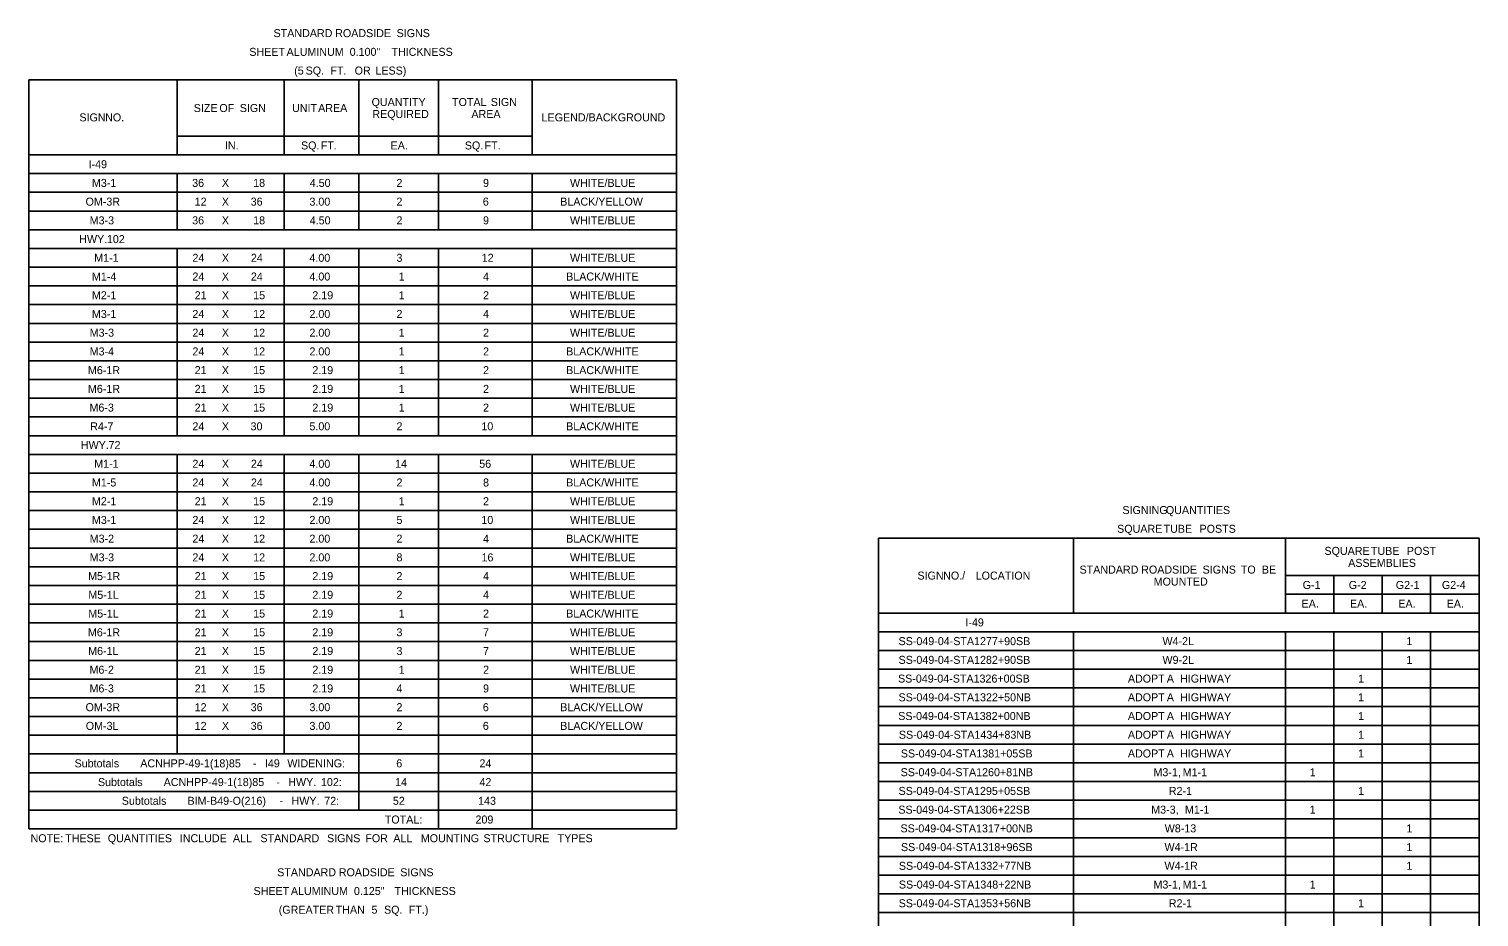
# Model space of a CAD drawing. Extents: x 1226613 to 1228135, y 151309 to 152326.
# Drawn here: x 1226613 to 1227428, y 151827 to 152326 of the extents above; entities that cross this region are included whole.
import ezdxf

# ---------------------------------------------------------------- set-up
doc = ezdxf.new("R2010")
doc.units = 0
doc.layers.add('R_Dimension', color=7, linetype='Continuous')

msp = doc.modelspace()

# ---------------------------------------------------------------- linework, layer by layer
at = {"layer": 'R_Dimension'}
for p, q in [((1226612.74, 152297.31), (1226976.91, 152297.31)), ((1226612.74, 151876.11), (1226612.74, 152297.31)), ((1226696.11, 152255.19), (1226696.11, 152297.31)), ((1226756.21, 152255.19), (1226756.21, 152297.31)), ((1226798.33, 152255.19), (1226798.33, 152297.31)), ((1226843.09, 152255.19), (1226843.09, 152297.31)), ((1226895.74, 152255.19), (1226895.74, 152297.31)), ((1226976.91, 151876.11), (1226976.91, 152297.31)), ((1226696.11, 152265.72), (1226895.74, 152265.72)), ((1226612.74, 152255.19), (1226976.91, 152255.19)), ((1226895.74, 152255.19), (1226976.91, 152255.19)), ((1226612.74, 152244.66), (1226976.91, 152244.66)), ((1226696.11, 152213.07), (1226696.11, 152244.66)), ((1226756.21, 152213.07), (1226756.21, 152244.66)), ((1226798.33, 152213.07), (1226798.33, 152244.66)), ((1226843.09, 152213.07), (1226843.09, 152244.66)), ((1226895.74, 152213.07), (1226895.74, 152244.66)), ((1226612.74, 152234.13), (1226976.91, 152234.13)), ((1226612.74, 152223.6), (1226976.91, 152223.6)), ((1226612.74, 152213.07), (1226976.91, 152213.07)), ((1226612.74, 152202.54), (1226976.91, 152202.54)), ((1226696.11, 152097.24), (1226696.11, 152202.54)), ((1226756.21, 152097.24), (1226756.21, 152202.54)), ((1226798.33, 152097.24), (1226798.33, 152202.54)), ((1226843.09, 152097.24), (1226843.09, 152202.54)), ((1226895.74, 152097.24), (1226895.74, 152202.54)), ((1226612.74, 152192.01), (1226976.91, 152192.01)), ((1226612.74, 152181.48), (1226976.91, 152181.48)), ((1226612.74, 152170.95), (1226976.91, 152170.95)), ((1226612.74, 152160.42), (1226976.91, 152160.42)), ((1226612.74, 152149.89), (1226976.91, 152149.89)), ((1226612.74, 152139.36), (1226976.91, 152139.36)), ((1226612.74, 152128.83), (1226976.91, 152128.83)), ((1226612.74, 152118.3), (1226976.91, 152118.3)), ((1226612.74, 152107.77), (1226976.91, 152107.77)), ((1226612.74, 152097.24), (1226976.91, 152097.24)), ((1226612.74, 152086.71), (1226976.91, 152086.71)), ((1226696.11, 151918.23), (1226696.11, 152086.71)), ((1226756.21, 151918.23), (1226756.21, 152086.71)), ((1226798.33, 151886.64), (1226798.33, 152086.71)), ((1226843.09, 151876.11), (1226843.09, 152086.71)), ((1226895.74, 151876.11), (1226895.74, 152086.71)), ((1226612.74, 152076.18), (1226976.91, 152076.18)), ((1226612.74, 152065.65), (1226976.91, 152065.65)), ((1226612.74, 152055.12), (1226976.91, 152055.12)), ((1226612.74, 152044.59), (1226976.91, 152044.59)), ((1227090.5, 152039.62), (1227428.34, 152039.62)), ((1227090.5, 151597.36), (1227090.5, 152039.62)), ((1227200.19, 151997.5), (1227200.19, 152039.62)), ((1227319.53, 151997.5), (1227319.53, 152039.62)), ((1227428.34, 151597.36), (1227428.34, 152039.62)), ((1226612.74, 152034.06), (1226976.91, 152034.06)), ((1226612.74, 152023.53), (1226976.91, 152023.53)), ((1227319.53, 152018.56), (1227428.34, 152018.56)), ((1227346.73, 151997.5), (1227346.73, 152018.56)), ((1227373.93, 151997.5), (1227373.93, 152018.56)), ((1227401.13, 151997.5), (1227401.13, 152018.56)), ((1226612.74, 152013), (1226976.91, 152013)), ((1226612.74, 152002.47), (1226976.91, 152002.47)), ((1227319.53, 152008.03), (1227428.34, 152008.03)), ((1227090.5, 151997.5), (1227428.34, 151997.5)), ((1226612.74, 151991.94), (1226976.91, 151991.94)), ((1227090.5, 151986.97), (1227428.34, 151986.97)), ((1227200.19, 151713.19), (1227200.19, 151986.97)), ((1227319.53, 151713.19), (1227319.53, 151986.97)), ((1227346.73, 151713.19), (1227346.73, 151986.97)), ((1227373.93, 151713.19), (1227373.93, 151986.97)), ((1227401.13, 151713.19), (1227401.13, 151986.97)), ((1226612.74, 151981.41), (1226976.91, 151981.41)), ((1226612.74, 151970.88), (1226976.91, 151970.88)), ((1227090.5, 151976.44), (1227428.34, 151976.44)), ((1227090.5, 151965.91), (1227428.34, 151965.91)), ((1226612.74, 151960.35), (1226976.91, 151960.35)), ((1227090.5, 151955.38), (1227428.34, 151955.38)), ((1226612.74, 151949.82), (1226976.91, 151949.82)), ((1226612.74, 151939.29), (1226976.91, 151939.29)), ((1227090.5, 151944.85), (1227428.34, 151944.85)), ((1226612.74, 151928.76), (1226976.91, 151928.76)), ((1227090.5, 151934.32), (1227428.34, 151934.32)), ((1227090.5, 151923.79), (1227428.34, 151923.79)), ((1226612.74, 151918.23), (1226976.91, 151918.23)), ((1227090.5, 151913.26), (1227428.34, 151913.26)), ((1226612.74, 151907.7), (1226976.91, 151907.7)), ((1226612.74, 151897.17), (1226976.91, 151897.17)), ((1227090.5, 151902.73), (1227428.34, 151902.73)), ((1227090.5, 151892.2), (1227428.34, 151892.2)), ((1226612.74, 151886.64), (1226976.91, 151886.64)), ((1227090.5, 151881.67), (1227428.34, 151881.67)), ((1226612.74, 151876.11), (1226976.91, 151876.11)), ((1227090.5, 151871.14), (1227428.34, 151871.14)), ((1227090.5, 151860.61), (1227428.34, 151860.61)), ((1227090.5, 151850.08), (1227428.34, 151850.08)), ((1227090.5, 151839.55), (1227428.34, 151839.55)), ((1227090.5, 151829.02), (1227428.34, 151829.02))]:
    msp.add_line(p, q, dxfattribs=at)

# ---------------------------------------------------------------- texts
for s, p in [('STANDARD', (1226750.3, 152321.39)), (' ROADSIDE', (1226783.29, 152321.39)), (' SIGNS', (1226817.84, 152321.39)), ('SHEET', (1226736.66, 152310.86)), (' ALUMINUM', (1226755.97, 152310.86)), (' 0.100"', (1226791.44, 152310.86)), (' THICKNESS', (1226814.97, 152310.86)), ('(5', (1226761.92, 152300.33)), (' SQ.', (1226766.67, 152300.33)), (' FT.', (1226780.6, 152300.33)), (' OR', (1226794.24, 152300.33)), (' LESS)', (1226805.93, 152300.33)), ('SIZE', (1226705.4, 152279.27)), (' OF', (1226718.15, 152279.27)), (' SIGN', (1226729.63, 152279.27)), ('UNIT', (1226760.71, 152279.27)), (' AREA', (1226773.71, 152279.27)), ('QUANTITY', (1226805.44, 152282.64)), ('REQUIRED', (1226805.88, 152275.89)), ('TOTAL', (1226850.7, 152282.64)), ('AREA', (1226861.6, 152275.89)), (' SIGN', (1226870.83, 152282.64)), ('SIGN', (1226641.1, 152274)), (' NO.', (1226653.89, 152274)), ('LEGEND/BACKGROUND', (1226901.08, 152274)), ('IN.', (1226722.94, 152258.21)), ('SQ.', (1226765.74, 152258.21)), (' FT.', (1226775.17, 152258.21)), ('EA.', (1226816.14, 152258.21)), ('SQ.', (1226857.88, 152258.21)), (' FT.', (1226867.3, 152258.21)), ('I-49', (1226646.27, 152247.68)), ('M3-1', (1226648.15, 152237.15)), ('36', (1226704.53, 152237.15)), ('X', (1226721.23, 152237.15)), ('18', (1226738.84, 152237.15)), ('4.50', (1226770.67, 152237.15)), ('2', (1226819.44, 152237.15)), ('9', (1226868.12, 152237.15)), ('WHITE/BLUE', (1226917.05, 152237.15)), ('OM-3R', (1226644.56, 152226.62)), ('12', (1226705.93, 152226.62)), ('X', (1226721.23, 152226.62)), ('36', (1226737.44, 152226.62)), ('3.00', (1226770.49, 152226.62)), ('2', (1226819.44, 152226.62)), ('6', (1226868.01, 152226.62)), ('BLACK/YELLOW', (1226911.55, 152226.62)), ('M3-3', (1226646.88, 152216.09)), ('36', (1226704.53, 152216.09)), ('X', (1226721.23, 152216.09)), ('18', (1226738.84, 152216.09)), ('4.50', (1226770.67, 152216.09)), ('2', (1226819.44, 152216.09)), ('9', (1226868.12, 152216.09)), ('WHITE/BLUE', (1226917.05, 152216.09)), ('HWY.', (1226641.01, 152205.56)), (' 102', (1226654.9, 152205.56)), ('M1-1', (1226649.43, 152195.03)), ('24', (1226704.66, 152195.03)), ('X', (1226721.23, 152195.03)), ('24', (1226737.56, 152195.03)), ('4.00', (1226770.49, 152195.03)), ('3', (1226819.44, 152195.03)), ('12', (1226867.39, 152195.03)), ('WHITE/BLUE', (1226917.05, 152195.03)), ('M1-4', (1226648.15, 152184.5)), ('24', (1226704.66, 152184.5)), ('X', (1226721.23, 152184.5)), ('24', (1226737.56, 152184.5)), ('4.00', (1226770.49, 152184.5)), ('1', (1226820.71, 152184.5)), ('4', (1226868.14, 152184.5)), ('BLACK/WHITE', (1226914.88, 152184.5)), ('M2-1', (1226648.15, 152173.97)), ('21', (1226705.93, 152173.97)), ('X', (1226721.23, 152173.97)), ('15', (1226738.84, 152173.97)), ('2.19', (1226772.12, 152173.97)), ('1', (1226820.71, 152173.97)), ('2', (1226868.14, 152173.97)), ('WHITE/BLUE', (1226917.05, 152173.97)), ('M3-1', (1226648.15, 152163.44)), ('24', (1226704.66, 152163.44)), ('X', (1226721.23, 152163.44)), ('12', (1226738.84, 152163.44)), ('2.00', (1226770.49, 152163.44)), ('2', (1226819.44, 152163.44)), ('4', (1226868.14, 152163.44)), ('WHITE/BLUE', (1226917.05, 152163.44)), ('M3-3', (1226646.88, 152152.91)), ('24', (1226704.66, 152152.91)), ('X', (1226721.23, 152152.91)), ('12', (1226738.84, 152152.91)), ('2.00', (1226770.49, 152152.91)), ('1', (1226820.71, 152152.91)), ('2', (1226868.14, 152152.91)), ('WHITE/BLUE', (1226917.05, 152152.91)), ('M3-4', (1226646.88, 152142.38)), ('24', (1226704.66, 152142.38)), ('X', (1226721.23, 152142.38)), ('12', (1226738.84, 152142.38)), ('2.00', (1226770.49, 152142.38)), ('1', (1226820.71, 152142.38)), ('2', (1226868.14, 152142.38)), ('BLACK/WHITE', (1226914.88, 152142.38)), ('M6-1R', (1226645.9, 152131.85)), ('21', (1226705.93, 152131.85)), ('X', (1226721.23, 152131.85)), ('15', (1226738.84, 152131.85)), ('2.19', (1226772.12, 152131.85)), ('1', (1226820.71, 152131.85)), ('2', (1226868.14, 152131.85)), ('BLACK/WHITE', (1226914.88, 152131.85)), ('M6-1R', (1226645.9, 152121.32)), ('21', (1226705.93, 152121.32)), ('X', (1226721.23, 152121.32)), ('15', (1226738.84, 152121.32)), ('2.19', (1226772.12, 152121.32)), ('1', (1226820.71, 152121.32)), ('2', (1226868.14, 152121.32)), ('WHITE/BLUE', (1226917.05, 152121.32)), ('M6-3', (1226646.77, 152110.79)), ('21', (1226705.93, 152110.79)), ('X', (1226721.23, 152110.79)), ('15', (1226738.84, 152110.79)), ('2.19', (1226772.12, 152110.79)), ('1', (1226820.71, 152110.79)), ('2', (1226868.14, 152110.79)), ('WHITE/BLUE', (1226917.05, 152110.79)), ('R4-7', (1226647.16, 152100.26)), ('24', (1226704.66, 152100.26)), ('X', (1226721.23, 152100.26)), ('30', (1226737.37, 152100.26)), ('5.00', (1226770.49, 152100.26)), ('2', (1226819.44, 152100.26)), ('10', (1226867.2, 152100.26)), ('BLACK/WHITE', (1226914.88, 152100.26)), ('HWY.', (1226641.93, 152089.73)), (' 72', (1226655.82, 152089.73)), ('M1-1', (1226649.43, 152079.2)), ('24', (1226704.66, 152079.2)), ('X', (1226721.23, 152079.2)), ('24', (1226737.56, 152079.2)), ('4.00', (1226770.49, 152079.2)), ('14', (1226818.69, 152079.2)), ('56', (1226865.99, 152079.2)), ('WHITE/BLUE', (1226917.05, 152079.2)), ('M1-5', (1226648.15, 152068.67)), ('24', (1226704.66, 152068.67)), ('X', (1226721.23, 152068.67)), ('24', (1226737.56, 152068.67)), ('4.00', (1226770.49, 152068.67)), ('2', (1226819.44, 152068.67)), ('8', (1226868.14, 152068.67)), ('BLACK/WHITE', (1226914.88, 152068.67)), ('M2-1', (1226648.15, 152058.14)), ('21', (1226705.93, 152058.14)), ('X', (1226721.23, 152058.14)), ('15', (1226738.84, 152058.14)), ('2.19', (1226772.12, 152058.14)), ('1', (1226820.71, 152058.14)), ('2', (1226868.14, 152058.14)), ('WHITE/BLUE', (1226917.05, 152058.14)), ('M3-1', (1226648.15, 152047.61)), ('24', (1226704.66, 152047.61)), ('X', (1226721.23, 152047.61)), ('12', (1226738.84, 152047.61)), ('2.00', (1226770.49, 152047.61)), ('5', (1226819.44, 152047.61)), ('10', (1226867.2, 152047.61)), ('WHITE/BLUE', (1226917.05, 152047.61)), ('SIGNING', (1227227.78, 152053.16)), (' QUANTITIES', (1227250.56, 152053.16)), ('SQUARE', (1227224.8, 152042.63)), (' TUBE', (1227249.25, 152042.63)), (' POSTS', (1227269.48, 152042.63)), ('M3-2', (1226646.88, 152037.08)), ('24', (1226704.66, 152037.08)), ('X', (1226721.23, 152037.08)), ('12', (1226738.84, 152037.08)), ('2.00', (1226770.49, 152037.08)), ('2', (1226819.44, 152037.08)), ('4', (1226868.14, 152037.08)), ('BLACK/WHITE', (1226914.88, 152037.08)), ('SQUARE', (1227341.42, 152030.21)), (' TUBE', (1227365.87, 152030.21)), (' POST', (1227386.1, 152030.21)), ('M3-3', (1226646.88, 152026.55)), ('24', (1226704.66, 152026.55)), ('X', (1226721.23, 152026.55)), ('12', (1226738.84, 152026.55)), ('2.00', (1226770.49, 152026.55)), ('8', (1226819.44, 152026.55)), ('16', (1226867.27, 152026.55)), ('WHITE/BLUE', (1226917.05, 152026.55)), ('ASSEMBLIES', (1227354.76, 152023.46)), ('M5-1R', (1226646.01, 152016.02)), ('21', (1226705.93, 152016.02)), ('X', (1226721.23, 152016.02)), ('15', (1226738.84, 152016.02)), ('2.19', (1226772.12, 152016.02)), ('2', (1226819.44, 152016.02)), ('4', (1226868.14, 152016.02)), ('WHITE/BLUE', (1226917.05, 152016.02)), ('SIGN', (1227112.48, 152016.31)), (' NO./', (1227125.27, 152016.31)), (' LOCATION', (1227143.55, 152016.31)), ('STANDARD', (1227203.66, 152019.68)), (' ROADSIDE', (1227236.65, 152019.68)), (' SIGNS', (1227271.19, 152019.68)), (' TO', (1227292.7, 152019.68)), (' BE', (1227304.54, 152019.68)), ('WHITE/BLUE', (1226917.05, 152005.49)), ('MOUNTED', (1227245.35, 152012.93)), ('G-1', (1227329.16, 152011.04)), ('G-2', (1227355.09, 152011.04)), ('G2-1', (1227381.54, 152011.04)), ('G2-4', (1227407.47, 152011.04)), ('M5-1L', (1226646.13, 152005.49)), ('21', (1226705.93, 152005.49)), ('X', (1226721.23, 152005.49)), ('15', (1226738.84, 152005.49)), ('2.19', (1226772.12, 152005.49)), ('2', (1226819.44, 152005.49)), ('4', (1226868.14, 152005.49)), ('EA.', (1227328.56, 152000.51)), ('EA.', (1227355.76, 152000.51)), ('EA.', (1227382.96, 152000.51)), ('EA.', (1227410.16, 152000.51)), ('M5-1L', (1226646.13, 151994.96)), ('21', (1226705.93, 151994.96)), ('X', (1226721.23, 151994.96)), ('15', (1226738.84, 151994.96)), ('2.19', (1226772.12, 151994.96)), ('1', (1226820.71, 151994.96)), ('2', (1226868.14, 151994.96)), ('BLACK/WHITE', (1226914.88, 151994.96)), ('I-49', (1227139.44, 151989.98)), ('M6-1R', (1226645.9, 151984.43)), ('21', (1226705.93, 151984.43)), ('X', (1226721.23, 151984.43)), ('15', (1226738.84, 151984.43)), ('2.19', (1226772.12, 151984.43)), ('3', (1226819.44, 151984.43)), ('7', (1226868.14, 151984.43)), ('WHITE/BLUE', (1226917.05, 151984.43)), ('M6-1L', (1226646.03, 151973.9)), ('21', (1226705.93, 151973.9)), ('X', (1226721.23, 151973.9)), ('15', (1226738.84, 151973.9)), ('2.19', (1226772.12, 151973.9)), ('3', (1226819.44, 151973.9)), ('7', (1226868.14, 151973.9)), ('WHITE/BLUE', (1226917.05, 151973.9)), ('SS-049-04-STA1277+90SB', (1227101.85, 151979.45)), ('W4-2L', (1227250.29, 151979.45)), ('1', (1227387.53, 151979.45)), ('SS-049-04-STA1282+90SB', (1227101.85, 151968.92)), ('W9-2L', (1227250.29, 151968.92)), ('1', (1227387.53, 151968.92)), ('M6-2', (1226646.77, 151963.37)), ('21', (1226705.93, 151963.37)), ('X', (1226721.23, 151963.37)), ('15', (1226738.84, 151963.37)), ('2.19', (1226772.12, 151963.37)), ('1', (1226820.71, 151963.37)), ('2', (1226868.14, 151963.37)), ('WHITE/BLUE', (1226917.05, 151963.37)), ('SS-049-04-STA1326+00SB', (1227101.56, 151958.39)), ('ADOPT', (1227230.84, 151958.39)), (' A', (1227251.07, 151958.39)), (' HIGHWAY', (1227258.51, 151958.39)), ('1', (1227360.33, 151958.39)), ('M6-3', (1226646.77, 151952.84)), ('21', (1226705.93, 151952.84)), ('X', (1226721.23, 151952.84)), ('15', (1226738.84, 151952.84)), ('2.19', (1226772.12, 151952.84)), ('4', (1226819.44, 151952.84)), ('9', (1226868.12, 151952.84)), ('WHITE/BLUE', (1226917.05, 151952.84)), ('OM-3R', (1226644.56, 151942.31)), ('12', (1226705.93, 151942.31)), ('X', (1226721.23, 151942.31)), ('36', (1226737.44, 151942.31)), ('3.00', (1226770.49, 151942.31)), ('2', (1226819.44, 151942.31)), ('6', (1226868.01, 151942.31)), ('BLACK/YELLOW', (1226911.55, 151942.31)), ('SS-049-04-STA1322+50NB', (1227101.85, 151947.86)), ('ADOPT', (1227230.84, 151947.86)), (' A', (1227251.07, 151947.86)), (' HIGHWAY', (1227258.51, 151947.86)), ('1', (1227360.33, 151947.86)), ('SS-049-04-STA1382+00NB', (1227101.67, 151937.33)), ('ADOPT', (1227230.84, 151937.33)), (' A', (1227251.07, 151937.33)), (' HIGHWAY', (1227258.51, 151937.33)), ('1', (1227360.33, 151937.33)), ('OM-3L', (1226644.68, 151931.78)), ('12', (1226705.93, 151931.78)), ('X', (1226721.23, 151931.78)), ('36', (1226737.44, 151931.78)), ('3.00', (1226770.49, 151931.78)), ('2', (1226819.44, 151931.78)), ('6', (1226868.01, 151931.78)), ('BLACK/YELLOW', (1226911.55, 151931.78)), ('SS-049-04-STA1434+83NB', (1227102.03, 151926.8)), ('ADOPT', (1227230.84, 151926.8)), (' A', (1227251.07, 151926.8)), (' HIGHWAY', (1227258.51, 151926.8)), ('1', (1227360.33, 151926.8)), ('SS-049-04-STA1381+05SB', (1227103.12, 151916.27)), ('ADOPT', (1227230.84, 151916.27)), (' A', (1227251.07, 151916.27)), (' HIGHWAY', (1227258.51, 151916.27)), ('1', (1227360.33, 151916.27)), ('Subtotals', (1226638.39, 151910.72)), (' ACNHPP-49-1(18)85', (1226673.68, 151910.72)), (' -', (1226737.07, 151910.72)), (' I49', (1226743.77, 151910.72)), (' WIDENING:', (1226756.39, 151910.72)), ('6', (1226819.31, 151910.72)), ('24', (1226866.12, 151910.72)), ('Subtotals', (1226651.54, 151900.19)), (' ACNHPP-49-1(18)85', (1226686.83, 151900.19)), (' HWY.', (1226756.92, 151900.19)), (' 102:', (1226775.31, 151900.19)), ('14', (1226818.69, 151900.19)), ('42', (1226866.12, 151900.19)), ('SS-049-04-STA1260+81NB', (1227103.02, 151905.74)), ('M3-1,', (1227245.24, 151905.74)), (' M1-1', (1227259.98, 151905.74)), ('1', (1227333.13, 151905.74)), (' -', (1226750.22, 151900.19)), ('SS-049-04-STA1295+05SB', (1227101.85, 151895.21)), ('R2-1', (1227253.87, 151895.21)), ('1', (1227360.33, 151895.21)), ('Subtotals', (1226664.93, 151889.66)), (' BIM-B49-O(216)', (1226700.22, 151889.66)), (' -', (1226752.06, 151889.66)), (' HWY.', (1226758.76, 151889.66)), (' 72:', (1226777.15, 151889.66)), ('52', (1226817.42, 151889.66)), ('143', (1226865.37, 151889.66)), ('SS-049-04-STA1306+22SB', (1227101.74, 151884.68)), ('M3-3,', (1227243.96, 151884.68)), (' M1-1', (1227261.26, 151884.68)), ('1', (1227333.13, 151884.68)), ('TOTAL:', (1226812.87, 151879.13)), ('209', (1226863.9, 151879.13)), ('NOTE:', (1226613.62, 151868.6)), (' THESE', (1226631.41, 151868.6)), (' QUANTITIES', (1226655.4, 151868.6)), (' INCLUDE', (1226695.9, 151868.6)), (' ALL', (1226725.77, 151868.6)), (' STANDARD', (1226741.25, 151868.6)), (' SIGNS', (1226778.74, 151868.6)), (' FOR', (1226800.25, 151868.6)), (' ALL', (1226815.98, 151868.6)), (' MOUNTING', (1226831.46, 151868.6)), (' STRUCTURE', (1226866.68, 151868.6)), (' TYPES', (1226908.39, 151868.6)), ('SS-049-04-STA1317+00NB', (1227102.95, 151874.15)), ('W8-13', (1227251.56, 151874.15)), ('1', (1227387.53, 151874.15)), ('SS-049-04-STA1318+96SB', (1227103.19, 151863.62)), ('W4-1R', (1227251.44, 151863.62)), ('1', (1227387.53, 151863.62)), ('SS-049-04-STA1332+77NB', (1227102.03, 151853.09)), ('W4-1R', (1227251.44, 151853.09)), ('1', (1227387.53, 151853.09)), ('STANDARD', (1226752.35, 151849.46)), (' ROADSIDE', (1226785.34, 151849.46)), (' SIGNS', (1226819.89, 151849.46)), ('SS-049-04-STA1348+22NB', (1227102.03, 151842.56)), ('M3-1,', (1227245.24, 151842.56)), (' M1-1', (1227259.98, 151842.56)), ('1', (1227333.13, 151842.56)), ('SHEET', (1226739.07, 151838.93)), (' ALUMINUM', (1226758.38, 151838.93)), (' 0.125"', (1226793.85, 151838.93)), (' THICKNESS', (1226816.67, 151838.93)), ('(GREATER', (1226753.22, 151828.4)), (' THAN', (1226783.59, 151828.4)), (' 5', (1226803.71, 151828.4)), (' SQ.', (1226810.77, 151828.4)), (' FT.)', (1226824.69, 151828.4)), ('SS-049-04-STA1353+56NB', (1227101.92, 151832.03)), ('R2-1', (1227253.87, 151832.03)), ('1', (1227360.33, 151832.03))]:
    msp.add_text(s, height=4.5, dxfattribs=at).set_placement(p)

doc.saveas('drawing.dxf')
